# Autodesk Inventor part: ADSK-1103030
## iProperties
Shininess: 41.0
Length Units: 11272
Angle Units: 11279
Time Units: 11290
Mass Units: 11286
Length Display Precision: 4
Angle Display Precision: 2
Compacted: True
Created: 2000-08
Part Number: ADSK-1103030
Document SubType Name: Modeling
Description: CLUTCH SHOE
Mass: 2.36913 g
Surface Area: 6.11189 cm^2
Volume: 0.525306 cm^3
Density: 4.51 g/cm^3
Material: Titanium
Density: 0.0
Volumn: 0.0
Area: 0.0
PropertySet Name: Model Information
Control State: 0
Master: False
Checked Out: False
